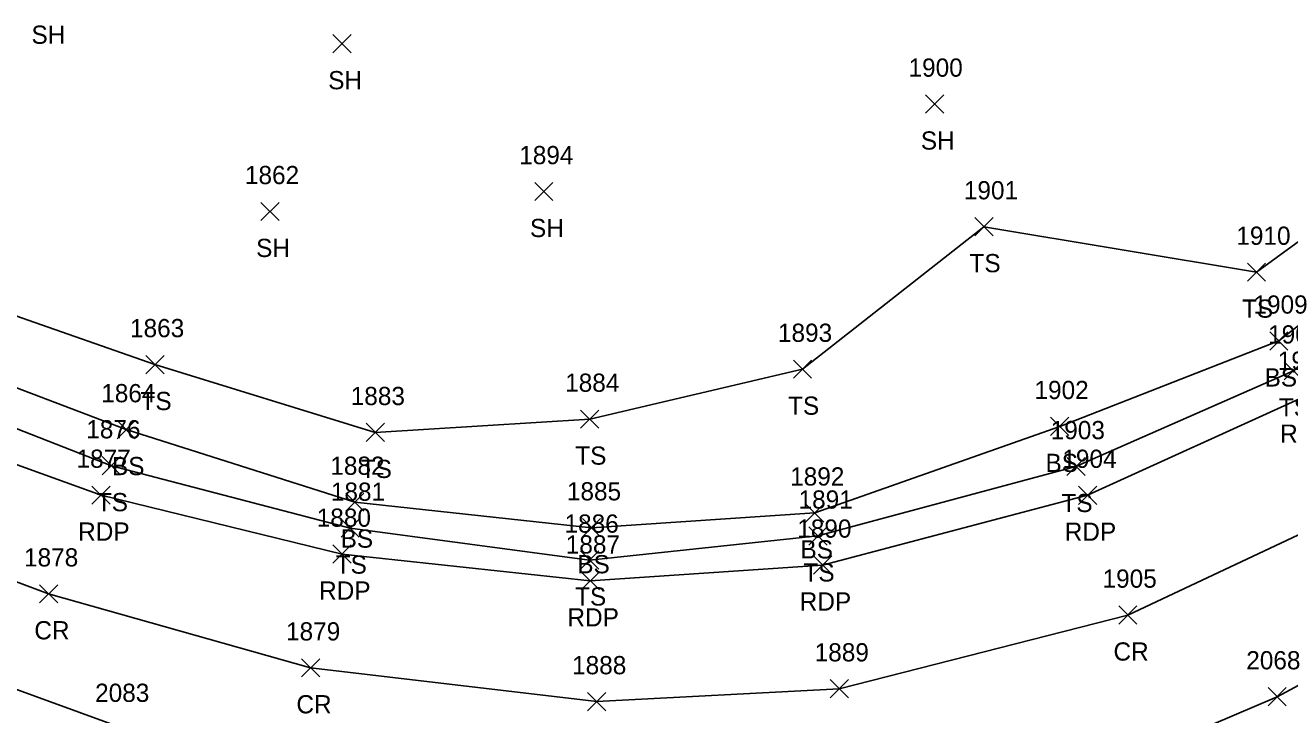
# Model space of a CAD drawing. Extents: x 1459992 to 1461532, y 647785 to 648535.
# Drawn here: x 1461117.9 to 1461256.6, y 648280.9 to 648356.5 of the extents above; entities that cross this region are included whole.
import ezdxf

# ---------------------------------------------------------------- set-up
doc = ezdxf.new("R2010")
doc.units = 0
for name, color, linetype in [('L_A', 7, 'Continuous'), ('L_I', 7, 'Continuous'), ('L_TIC', 7, 'Continuous'), ('LELB', 7, 'Continuous'), ('P_A', 7, 'Continuous'), ('P_I', 7, 'Continuous'), ('P_TIC', 7, 'Continuous'), ('PET', 7, 'Continuous'), ('PRC', 7, 'Continuous')]:
    doc.layers.add(name, color=color, linetype=linetype)

msp = doc.modelspace()

# ---------------------------------------------------------------- linework, layer by layer
at = {"layer": 'L_TIC'}
for points in [[(1461151.61, 648353.49), (1461153.61, 648355.49)], [(1461153.61, 648353.49), (1461151.61, 648355.49)], [(1461216.64, 648346.87), (1461218.64, 648348.87)], [(1461218.64, 648346.87), (1461216.64, 648348.87)], [(1461173.76, 648337.27), (1461175.76, 648339.27)], [(1461175.76, 648337.27), (1461173.76, 648339.27)], [(1461143.7, 648335.08), (1461145.7, 648337.08)], [(1461145.7, 648335.08), (1461143.7, 648337.08)], [(1461222.06, 648333.41), (1461224.06, 648335.41)], [(1461224.06, 648333.41), (1461222.06, 648335.41)], [(1461251.96, 648328.42), (1461253.96, 648330.42)], [(1461253.96, 648328.42), (1461251.96, 648330.42)], [(1461254.41, 648320.87), (1461256.41, 648322.87)], [(1461256.41, 648320.87), (1461254.41, 648322.87)], [(1461131.09, 648318.28), (1461133.09, 648320.28)], [(1461133.09, 648318.28), (1461131.09, 648320.28)], [(1461202.15, 648317.77), (1461204.15, 648319.77)], [(1461204.15, 648317.77), (1461202.15, 648319.77)], [(1461256.01, 648317.59), (1461258.01, 648319.59)], [(1461258.01, 648317.59), (1461256.01, 648319.59)], [(1461178.8, 648312.29), (1461180.8, 648314.29)], [(1461180.8, 648312.29), (1461178.8, 648314.29)], [(1461230.37, 648311.49), (1461232.37, 648313.49)], [(1461232.37, 648311.49), (1461230.37, 648313.49)], [(1461127.93, 648311.14), (1461129.93, 648313.14)], [(1461129.93, 648311.14), (1461127.93, 648313.14)], [(1461155.26, 648310.83), (1461157.26, 648312.83)], [(1461157.26, 648310.83), (1461155.26, 648312.83)], [(1461126.3, 648307.18), (1461128.3, 648309.18)], [(1461128.3, 648307.18), (1461126.3, 648309.18)], [(1461232.15, 648307.09), (1461234.15, 648309.09)], [(1461234.15, 648307.09), (1461232.15, 648309.09)], [(1461153.02, 648303.18), (1461155.02, 648305.18)], [(1461155.02, 648303.18), (1461153.02, 648305.18)], [(1461203.48, 648302), (1461205.48, 648304)], [(1461205.48, 648302), (1461203.48, 648304)], [(1461152.51, 648300.33), (1461154.51, 648302.33)], [(1461154.51, 648300.33), (1461152.51, 648302.33)], [(1461178.99, 648300.37), (1461180.99, 648302.37)], [(1461180.99, 648300.37), (1461178.99, 648302.37)], [(1461203.84, 648299.47), (1461205.84, 648301.47)], [(1461205.84, 648299.47), (1461203.84, 648301.47)], [(1461178.78, 648296.83), (1461180.78, 648298.83)], [(1461180.78, 648296.83), (1461178.78, 648298.83)]]:
    msp.add_lwpolyline(points, dxfattribs=at)
at = {"layer": 'LELB'}
for points in [[(1461053.3, 648342.88), (1461057.1, 648347.56), (1461103.6, 648329.25), (1461132.09, 648319.28), (1461156.26, 648311.83), (1461179.8, 648313.29), (1461203.15, 648318.77), (1461223.06, 648334.41), (1461252.96, 648329.42), (1461275.76, 648346.01), (1461293.92, 648360.57), (1461297.9, 648376.52), (1461309.92, 648382.32), (1461323.28, 648384.14), (1461344.65, 648406.6), (1461362.09, 648421.03), (1461389.72, 648443.02), (1461411.96, 648455.77)], [(1461045.75, 648345.16), (1461053.3, 648342.88), (1461099.57, 648323.3), (1461128.93, 648312.14), (1461154.02, 648304.18), (1461179.99, 648301.37), (1461204.48, 648303), (1461231.37, 648312.49), (1461255.41, 648321.87), (1461278.91, 648340.15), (1461298.64, 648355.28), (1461307.84, 648362.71), (1461328.64, 648380.09), (1461350.69, 648401.06), (1461366.77, 648414.15), (1461392.6, 648435.99), (1461415.7, 648449.6)], [(1460952.34, 648377.13), (1460985.69, 648362.66), (1461027.43, 648346.63), (1461054.39, 648335.28), (1461097.58, 648319.81), (1461127.3, 648308.18), (1461153.51, 648301.33), (1461179.78, 648297.83), (1461204.84, 648300.47), (1461233.15, 648308.09), (1461257.01, 648318.59), (1461281.51, 648336.52), (1461300.79, 648352.57), (1461310.07, 648360.68), (1461331.77, 648379.2), (1461352.47, 648399.38), (1461367.35, 648413.21), (1461394.44, 648433.89), (1461417.38, 648445.8)]]:
    msp.add_lwpolyline(points, dxfattribs=at)
at = {"layer": 'P_TIC'}
for points in [[(1461125.17, 648303.95), (1461127.17, 648305.95)], [(1461127.17, 648303.95), (1461125.17, 648305.95)], [(1461233.43, 648303.94), (1461235.43, 648305.94)], [(1461235.43, 648303.94), (1461233.43, 648305.94)], [(1461151.62, 648297.48), (1461153.62, 648299.48)], [(1461153.62, 648297.48), (1461151.62, 648299.48)], [(1461204.35, 648296.28), (1461206.35, 648298.28)], [(1461206.35, 648296.28), (1461204.35, 648298.28)], [(1461178.86, 648294.54), (1461180.86, 648296.54)], [(1461180.86, 648294.54), (1461178.86, 648296.54)], [(1461119.42, 648293.12), (1461121.42, 648295.12)], [(1461121.42, 648293.12), (1461119.42, 648295.12)], [(1461237.84, 648290.79), (1461239.84, 648292.79)], [(1461239.84, 648290.79), (1461237.84, 648292.79)], [(1461148.17, 648285), (1461150.17, 648287)], [(1461150.17, 648285), (1461148.17, 648287)], [(1461206.18, 648282.7), (1461208.18, 648284.7)], [(1461208.18, 648282.7), (1461206.18, 648284.7)], [(1461179.56, 648281.29), (1461181.56, 648283.29)], [(1461181.56, 648281.29), (1461179.56, 648283.29)], [(1461254.23, 648281.83), (1461256.23, 648283.83)], [(1461256.23, 648281.83), (1461254.23, 648283.83)]]:
    msp.add_lwpolyline(points, dxfattribs=at)
at = {"layer": 'PET'}
for points in [[(1460950.93, 648374.58), (1460984.69, 648360.32), (1461025.42, 648343.73), (1461053.38, 648332.51), (1461095.05, 648316.17), (1461126.17, 648304.95), (1461152.62, 648298.48), (1461179.86, 648295.54), (1461205.35, 648297.28), (1461234.43, 648304.94), (1461258.07, 648315.7), (1461283.68, 648333.5), (1461302.87, 648349.75), (1461333.02, 648377.55), (1461355.02, 648397.13), (1461371.06, 648410.57), (1461396.62, 648429.43), (1461418.97, 648443.38)], [(1461431.71, 648423.56), (1461406.61, 648408.47), (1461395.32, 648400.74), (1461379.71, 648387.97), (1461360, 648370.89), (1461342.5, 648355.32), (1461322.76, 648336.16), (1461306.54, 648318.18), (1461292.23, 648305.65), (1461275.7, 648293.86), (1461255.23, 648282.83), (1461238.6, 648275.7), (1461226.2, 648272.49), (1461213.09, 648269.85), (1461197.04, 648267.63), (1461176.94, 648267.36), (1461164.21, 648269.58)], [(1460942.85, 648353.98), (1460975.34, 648340.07), (1461016.08, 648323.29), (1461041.44, 648312.66), (1461070.03, 648301.09), (1461083.95, 648295.62), (1461128.85, 648279.26), (1461164.21, 648269.58), (1461178.63, 648262.65), (1461203.09, 648251.99), (1461227.86, 648243.02), (1461244.86, 648238.13), (1461258.8, 648233.38), (1461270.23, 648226.19), (1461279.65, 648219.62), (1461287.61, 648211.81)]]:
    msp.add_lwpolyline(points, dxfattribs=at)
at = {"layer": 'PRC'}
msp.add_lwpolyline([(1460946.83, 648364.55), (1460979.81, 648350.87), (1461020.89, 648333.41), (1461048.05, 648322.3), (1461089.53, 648305.67), (1461120.42, 648294.12), (1461149.17, 648286), (1461180.56, 648282.29), (1461207.18, 648283.7), (1461238.84, 648291.79), (1461263.78, 648303.51), (1461290.77, 648322.92), (1461310.31, 648340.94), (1461342.22, 648370.37), (1461365.17, 648390.4), (1461371.57, 648396.04), (1461402.62, 648419.98), (1461424.86, 648433.53)], dxfattribs=at)

# ---------------------------------------------------------------- texts
at = {"layer": 'L_A'}
for s, p in [('SH', (1461118.54, 648354.48)), ('SH', (1461151.1, 648349.49)), ('SH', (1461216.13, 648342.87)), ('SH', (1461173.24, 648333.27)), ('SH', (1461143.19, 648331.08)), ('TS', (1461221.47, 648329.41)), ('TS', (1461251.37, 648324.42)), ('BS', (1461253.85, 648316.87)), ('TS', (1461130.5, 648314.28)), ('TS', (1461201.56, 648313.77)), ('TS', (1461255.42, 648313.59)), ('TS', (1461178.21, 648308.29)), ('BS', (1461229.81, 648307.49)), ('BS', (1461127.37, 648307.14)), ('TS', (1461154.67, 648306.83)), ('TS', (1461125.71, 648303.18)), ('TS', (1461231.56, 648303.09)), ('BS', (1461152.46, 648299.18)), ('BS', (1461202.92, 648298)), ('TS', (1461151.92, 648296.33)), ('BS', (1461178.43, 648296.37)), ('TS', (1461203.25, 648295.47)), ('TS', (1461178.19, 648292.83))]:
    msp.add_text(s, height=2, dxfattribs=at).set_placement(p)
at = {"layer": 'L_I'}
for s, p in [('1900', (1461214.78, 648350.87)), ('1894', (1461172.06, 648341.27)), ('1862', (1461141.96, 648339.08)), ('1901', (1461220.85, 648337.41)), ('1910', (1461250.75, 648332.42)), ('1909', (1461252.63, 648324.87)), ('1863', (1461129.35, 648322.28)), ('1893', (1461200.45, 648321.77)), ('1908', (1461254.24, 648321.59)), ('1884', (1461177.1, 648316.29)), ('1864', (1461126.19, 648315.14)), ('1883', (1461153.57, 648314.83)), ('1902', (1461228.6, 648315.49)), ('1876', (1461124.55, 648311.18)), ('1903', (1461230.38, 648311.09)), ('1882', (1461151.33, 648307.18)), ('1892', (1461201.79, 648306)), ('1881', (1461151.39, 648304.33)), ('1885', (1461177.29, 648304.37)), ('1891', (1461202.71, 648303.47)), ('1886', (1461177.03, 648300.83))]:
    msp.add_text(s, height=2, dxfattribs=at).set_placement(p)
at = {"layer": 'P_A'}
for s, p in [('RDP', (1461255.56, 648310.7)), ('RDP', (1461123.66, 648299.95)), ('RDP', (1461231.92, 648299.94)), ('RDP', (1461150.1, 648293.48)), ('RDP', (1461202.84, 648292.28)), ('RDP', (1461177.35, 648290.54)), ('CR', (1461118.85, 648289.12)), ('CR', (1461237.27, 648286.79)), ('CR', (1461147.61, 648281))]:
    msp.add_text(s, height=2, dxfattribs=at).set_placement(p)
at = {"layer": 'P_I'}
for s, p in [('1907', (1461255.3, 648318.7)), ('1877', (1461123.48, 648307.95)), ('1904', (1461231.66, 648307.94)), ('1880', (1461149.84, 648301.48)), ('1890', (1461202.57, 648300.28)), ('1887', (1461177.17, 648298.54)), ('1878', (1461117.72, 648297.12)), ('1905', (1461236.07, 648294.79)), ('1879', (1461146.47, 648289)), ('1889', (1461204.48, 648286.7)), ('1888', (1461177.86, 648285.29)), ('2068', (1461251.84, 648285.83)), ('2083', (1461125.52, 648282.26))]:
    msp.add_text(s, height=2, dxfattribs=at).set_placement(p)

doc.saveas('drawing.dxf')
